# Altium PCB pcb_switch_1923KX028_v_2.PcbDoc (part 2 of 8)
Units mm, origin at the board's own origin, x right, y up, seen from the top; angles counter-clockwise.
Board outline 297.2 x 112.05 mm, 6 copper layers (Component Side, GND Layer 1, Inner Layer 1, Inner Layer 2, GND Layer 2, Solder Side), stack 1.578 mm thick; 545 components, 377 nets, 3174 pads, 1537 vias.
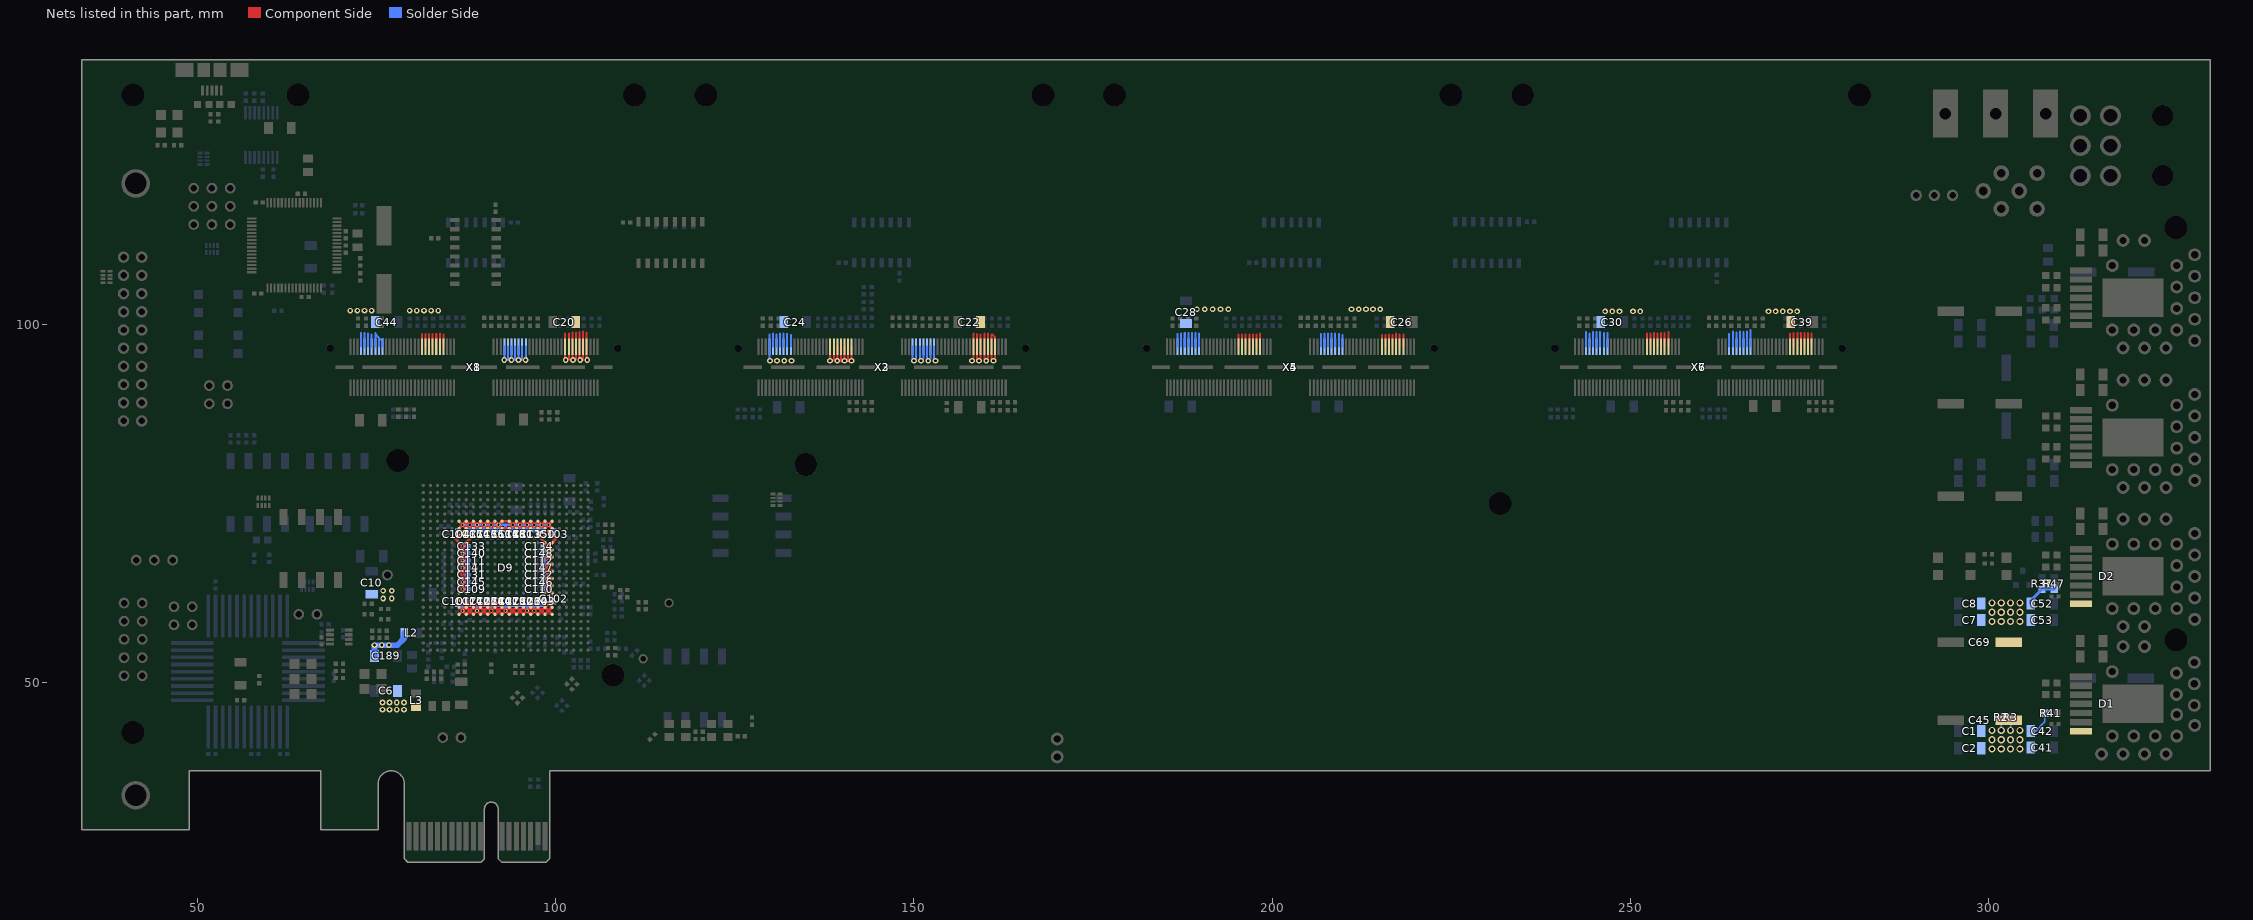
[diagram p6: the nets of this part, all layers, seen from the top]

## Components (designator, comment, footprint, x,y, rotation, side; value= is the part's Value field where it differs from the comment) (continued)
SA6 "DMHA-04G-G" FOOTPRINT_DMHA-04G-G 69.5,76.5 r0 bottom locked
SB1 "7914G-1-000 Е" 7914G_1_000_E 52.9,97.2 r90 bottom
SB2 "7914G-1-000 Е" 7914G_1_000_E 52.9,102.9 r90 bottom
VD1 "KP-2012SYCK" FOOTPRINT_SMD_LED_2.0x1.25mm 302.5,66.2 r270 top
VD2 "KP-2012SYCK" FOOTPRINT_SMD_LED_2.0x1.25mm 297.5,66.2 r270 top
VD3 "KP-2012SYCK" FOOTPRINT_SMD_LED_2.0x1.25mm 47.2,128 r270 top
VD4 "KP-2012SYCK" FOOTPRINT_SMD_LED_2.0x1.25mm 293,66.2 r270 top
VD5 "KP-2012SYCK" FOOTPRINT_SMD_LED_2.0x1.25mm 64.7,52.6 r180 top
VD6 "KP-2012SYCK" FOOTPRINT_SMD_LED_2.0x1.25mm 64.7,50.5 r180 top
VD7 "KP-2012SYCK" FOOTPRINT_SMD_LED_2.0x1.25mm 64.7,48.4 r180 top
VD8 "KP-2012SYCK" FOOTPRINT_SMD_LED_2.0x1.25mm 74.5,49.1 r180 top
VD9 "KP-2012SYCK" FOOTPRINT_SMD_LED_2.0x1.25mm 74.5,51.2 r180 top
VD10 "KP-2012SYCK" FOOTPRINT_SMD_LED_2.0x1.25mm 44.9,128 r270 top
VT1 "BC846B" FOOTPRINT_SOT-23 304.8,64.6 r0 bottom
X1 "qsh-60-01-f-d-a" QSH-60-01-F-D-A#1 70.5,94 r0 top
X2 "qsh-60-01-f-d-a" QSH-60-01-F-D-A#1 127.5,94 r0 top locked
X3 "qsh-60-01-f-d-a" QSH-60-01-F-D-A#2 163.63,94 r180 bottom locked
X4 "qsh-60-01-f-d-a" QSH-60-01-F-D-A#1 184.5,94 r0 top locked
X5 "qsh-60-01-f-d-a" QSH-60-01-F-D-A#2 220.63,94 r180 bottom locked
X6 "qsh-60-01-f-d-a" QSH-60-01-F-D-A#1 241.5,94 r0 top locked
X7 "qsh-60-01-f-d-a" QSH-60-01-F-D-A#2 277.63,94 r180 bottom locked
X8 "qsh-60-01-f-d-a" QSH-60-01-F-D-A#2 106.63,94 r180 bottom
X9 "10104110-0001LF" 10104110-0001LF 52,135.5 r180 top
X10 "WF-3" FOOTPRINT_WF-3 295,118 r180 top
X11 "IDC-20MS" IDC-20MS 39.66,86.5 r270 bottom locked
X12 "45558-0003" 45558-0003 324.35,124.925 r270 top
X13 "hole d=1mm" FOOTPRINT_TESTPOINT#1 76.5,65 r90 top
X14 "hole d=1mm" FOOTPRINT_TESTPOINT#2 112.2,53.3 r90 top
X15 "hole d=1mm" FOOTPRINT_TESTPOINT#3 115.8,61.1 r90 top
X16 "PCI_E x1" PCI_E_x1 91,28.5 r0 top locked
XP1 "PLS-2" PLS-2#1 49.24,59.3 r270 top locked
XP2 "PLS-2" PLS-2#1 85.5,42.3 r0 top
XP3 "PLS-2" PLS-2#1 46.7,59.3 r270 top locked
XP4 "PLS-3" PLS-3 43.97,67.08 r0 top
XP5 "PLD-10" FOOTPRINT_PLD10 41,56 r90 bottom
XP6 "PLS-2" PLS-2#2 52.9,88.9 r180 bottom locked
XP7 "PLS-2" PLS-2#2 52.9,91.44 r180 bottom locked
XP8 "PLS-3" PLS-3 52,119 r0 bottom
XP9 "PLS-3" PLS-3 52,116.46 r0 bottom
XP10 "PLS-3" PLS-3 52,113.92 r0 bottom
XP11 "PLS-2" PLS-2#1 65.4,59.5 r0 top
Z1 "BNX016" BNX016 306.8,116.1 r180 bottom

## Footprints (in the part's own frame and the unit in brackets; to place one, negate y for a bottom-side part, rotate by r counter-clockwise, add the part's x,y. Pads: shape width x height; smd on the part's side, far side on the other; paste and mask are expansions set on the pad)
7914G_1_000_E [mm] "smd key, 5 x 5mm"
  rect 1.27x1.27 smd mask+0.05: 1(-1.27,2.75) 2(1.27,2.75) 3(1.27,-2.75) 4(-1.27,-2.75)
  silkscreen extent -2.5,-2.5 2.5,2.5
45558-0003 [mm] "PCI-Express Card Power Connector"
  round 2.9 hole 1.9 mask+0.1: 1(-4.2,-7.3) 2(0,-7.3) 3(4.2,-7.3) 4(-4.2,-11.5) 5(0,-11.5) 6(4.2,-11.5)
  round 3 hole 3 unplated mask+0.1: 7(-4.2,0) 8(4.2,0)
  silkscreen extent -6.9,-6.2 6.9,6.6
10104110-0001LF [mm] "micro USB B receptacle"
  rect 0.4x1.4 smd mask+0.05: 1(-1.3,2.85) 2(-0.65,2.85) 3(0,2.85) 4(0.65,2.85) 5(1.3,2.85)
  rect 2.5x1.9 smd mask+0.05: 6(-3.85,0) 9(3.85,0)
  rect 1.8x1.9 smd mask+0.05: 7(-1.15,0) 8(1.15,0)
  silkscreen extent -3.75,-1.45 3.75,2.85
BNX016 [mm] "BNX016, Block Type EMIFIL"
  round 2.2 hole 1.2 mask+0.05: 1(5,5) 2(5,0) 3(0,5) 4(0,0) 5(2.5,2.5) 6(7.5,2.5)
  silkscreen extent -3.5,-3 8.5,8
FOOTPRINT_0402 [mm] "0402"
  rect 0.6x0.6 smd mask+0.05: 1(-0.5,0) 2(0.5,0)
  silkscreen extent -1.02,-0.53 1.02,0.53
FOOTPRINT_0603 [mm]
  rect 1x1 smd mask+0.1: 1(-0.8,0) 2(0.8,0)
  silkscreen extent -1.53,-0.73 1.53,0.73
FOOTPRINT_0804_RES_ARRAY [mm] "4 isolated resistor in an 0804 size package"
  rect 0.4x0.7 smd mask+0.05: 1(-0.8,-0.5) 4(0.8,-0.5) 5(-0.8,0.5) 8(0.8,0.5)
  rect 0.3x0.7 smd mask+0.05: 2(-0.25,-0.5) 3(0.25,-0.5) 6(-0.25,0.5) 7(0.25,0.5)
  silkscreen extent -1.07,-0.93 1.07,0.92
FOOTPRINT_0805 [mm] "0805"
  rect 1.1x1.4 smd mask+0.1: 1(-0.95,0) 2(0.95,0)
  silkscreen extent -1.78,-0.98 1.78,0.98
FOOTPRINT_1206#1 [mm] "SMD 1206, 10uF, 10%, 25V, X5R"
  rect 1.2x1.7 smd mask+0.05: 1(-1.6,0) 2(1.6,0)
  silkscreen extent -2.43,-1.08 2.43,1.07
FOOTPRINT_1206#2 [mm] "SMD 1206, 10uF, 10%, 25V, X5R"
  rect 1.2x1.7 smd: 1(-1.6,0) 2(1.6,0)
  silkscreen extent -2.43,-1.08 2.43,1.07
FOOTPRINT_DMHA-04G-G [mm] "DIP SWITCH 4"
  rect 1.1x2.2 smd mask+0.05: 1(-3.81,-4.4) 2(-1.27,-4.4) 3(1.27,-4.4) 4(3.81,-4.4) 5(3.81,4.4) 6(1.27,4.4) 7(-1.27,4.4) 8(-3.81,4.4)
  silkscreen extent -5.08,-3 5.08,3
FOOTPRINT_H14.42-1B [mm] "12 x 12 mm, step 1.0mm, 42 pins,"
  rect 6x0.5 smd mask+0.05: 1(-7.75,-0.5) 2(-7.75,-1.5) 3(-7.75,-2.5) 4(-7.75,-3.5) 5(-7.75,-4.5) 6(-7.75,-5.5) 16(7.75,-5.5) 17(7.75,-4.5) 18(7.75,-3.5) 19(7.75,-2.5) 20(7.75,-1.5) 21(7.75,-0.5) 22(7.75,0.5) 23(7.75,1.5) 24(7.75,2.5) 25(7.75,3.5) 26(7.75,4.5) 27(7.75,5.5) 37(-7.75,5.5) 38(-7.75,4.5) 39(-7.75,3.5) 40(-7.75,2.5) 41(-7.75,1.5) 42(-7.75,0.5)
  rect 0.5x6 smd mask+0.05: 7(-4,-7.75) 8(-3,-7.75) 9(-2,-7.75) 10(-1,-7.75) 11(0,-7.75) 12(1,-7.75) 13(2,-7.75) 14(3,-7.75) 15(4,-7.75) 28(4,7.75) 29(3,7.75) 30(2,7.75) 31(1,7.75) 32(0,7.75) 33(-1,7.75) 34(-2,7.75) 35(-3,7.75) 36(-4,7.75)
  silkscreen extent -6,-6 6,6
FOOTPRINT_KX7 [mm] "GEYER 12.88667 25MHz, 30ppm"
  rect 1.3x1.1 smd mask+0.1: 1(-1.15,-0.9) 2(1.15,-0.9) 3(1.15,0.9) 4(-1.15,0.9)
  silkscreen extent -1.8,-2.3 1.6,1.25
FOOTPRINT_MK8303.576-1 [mm] "BGA 25x25 mm, pitch 1 mm, d = 0.6 mm, 576 balls"
  round 0.45 smd mask+0.05: A1(-11.5,11.5) A2(-10.5,11.5) A3(-9.5,11.5) A4(-8.5,11.5) A5(-7.5,11.5) A6(-6.5,11.5) A7(-5.5,11.5) A8(-4.5,11.5) A9(-3.5,11.5) A10(-2.5,11.5) A11(-1.5,11.5) A12(-0.5,11.5) A13(0.5,11.5) A14(1.5,11.5) A15(2.5,11.5) A16(3.5,11.5) A17(4.5,11.5) A18(5.5,11.5) A19(6.5,11.5) A20(7.5,11.5) A21(8.5,11.5) A22(9.5,11.5) A23(10.5,11.5) A24(11.5,11.5) AA1(-11.5,-8.5) AA2(-10.5,-8.5) AA3(-9.5,-8.5) AA4(-8.5,-8.5) AA5(-7.5,-8.5) AA6(-6.5,-8.5) AA7(-5.5,-8.5) AA8(-4.5,-8.5) AA9(-3.5,-8.5) AA10(-2.5,-8.5) AA11(-1.5,-8.5) AA12(-0.5,-8.5) AA13(0.5,-8.5) AA14(1.5,-8.5) AA15(2.5,-8.5) AA16(3.5,-8.5) AA17(4.5,-8.5) AA18(5.5,-8.5) AA19(6.5,-8.5) AA20(7.5,-8.5) AA21(8.5,-8.5) AA22(9.5,-8.5) AA23(10.5,-8.5) AA24(11.5,-8.5) AB1(-11.5,-9.5) AB2(-10.5,-9.5) AB3(-9.5,-9.5) AB4(-8.5,-9.5) AB5(-7.5,-9.5) AB6(-6.5,-9.5) AB7(-5.5,-9.5) AB8(-4.5,-9.5) AB9(-3.5,-9.5) AB10(-2.5,-9.5) AB11(-1.5,-9.5) AB12(-0.5,-9.5) AB13(0.5,-9.5) AB14(1.5,-9.5) AB15(2.5,-9.5) AB16(3.5,-9.5) AB17(4.5,-9.5) AB18(5.5,-9.5) AB19(6.5,-9.5) AB20(7.5,-9.5) AB21(8.5,-9.5) AB22(9.5,-9.5) AB23(10.5,-9.5) AB24(11.5,-9.5) AC1(-11.5,-10.5) AC2(-10.5,-10.5) AC3(-9.5,-10.5) AC4(-8.5,-10.5) AC5(-7.5,-10.5) AC6(-6.5,-10.5) AC7(-5.5,-10.5) AC8(-4.5,-10.5) AC9(-3.5,-10.5) AC10(-2.5,-10.5) AC11(-1.5,-10.5) AC12(-0.5,-10.5) AC13(0.5,-10.5) AC14(1.5,-10.5) AC15(2.5,-10.5) AC16(3.5,-10.5) AC17(4.5,-10.5) AC18(5.5,-10.5) AC19(6.5,-10.5) AC20(7.5,-10.5) AC21(8.5,-10.5) AC22(9.5,-10.5) AC23(10.5,-10.5) AC24(11.5,-10.5) AD1(-11.5,-11.5) AD2(-10.5,-11.5) AD3(-9.5,-11.5) AD4(-8.5,-11.5) AD5(-7.5,-11.5) AD6(-6.5,-11.5) AD7(-5.5,-11.5) AD8(-4.5,-11.5) AD9(-3.5,-11.5) AD10(-2.5,-11.5) AD11(-1.5,-11.5) AD12(-0.5,-11.5) AD13(0.5,-11.5) AD14(1.5,-11.5) AD15(2.5,-11.5) AD16(3.5,-11.5) AD17(4.5,-11.5) AD18(5.5,-11.5) AD19(6.5,-11.5) AD20(7.5,-11.5) AD21(8.5,-11.5) AD22(9.5,-11.5) AD23(10.5,-11.5) AD24(11.5,-11.5) B1(-11.5,10.5) B2(-10.5,10.5) B3(-9.5,10.5) B4(-8.5,10.5) B5(-7.5,10.5) B6(-6.5,10.5) B7(-5.5,10.5) B8(-4.5,10.5) B9(-3.5,10.5) B10(-2.5,10.5) B11(-1.5,10.5) B12(-0.5,10.5) B13(0.5,10.5) B14(1.5,10.5) B15(2.5,10.5) B16(3.5,10.5) B17(4.5,10.5) B18(5.5,10.5) B19(6.5,10.5) B20(7.5,10.5) B21(8.5,10.5) B22(9.5,10.5) B23(10.5,10.5) B24(11.5,10.5) C1(-11.5,9.5) C2(-10.5,9.5) C3(-9.5,9.5) C4(-8.5,9.5) C5(-7.5,9.5) C6(-6.5,9.5) C7(-5.5,9.5) C8(-4.5,9.5) C9(-3.5,9.5) C10(-2.5,9.5) C11(-1.5,9.5) C12(-0.5,9.5) C13(0.5,9.5) C14(1.5,9.5) C15(2.5,9.5) C16(3.5,9.5) C17(4.5,9.5) C18(5.5,9.5) C19(6.5,9.5) C20(7.5,9.5) C21(8.5,9.5) C22(9.5,9.5) C23(10.5,9.5) C24(11.5,9.5) D1(-11.5,8.5) D2(-10.5,8.5) D3(-9.5,8.5) D4(-8.5,8.5) D5(-7.5,8.5) D6(-6.5,8.5) D7(-5.5,8.5) D8(-4.5,8.5) D9(-3.5,8.5) D10(-2.5,8.5) D11(-1.5,8.5) D12(-0.5,8.5) D13(0.5,8.5) D14(1.5,8.5) D15(2.5,8.5) D16(3.5,8.5) D17(4.5,8.5) D18(5.5,8.5) D19(6.5,8.5) D20(7.5,8.5) D21(8.5,8.5) D22(9.5,8.5) D23(10.5,8.5) D24(11.5,8.5) E1(-11.5,7.5) E2(-10.5,7.5) E3(-9.5,7.5) E4(-8.5,7.5) E5(-7.5,7.5) E6(-6.5,7.5) E7(-5.5,7.5) E8(-4.5,7.5) E9(-3.5,7.5) E10(-2.5,7.5) E11(-1.5,7.5) E12(-0.5,7.5) E13(0.5,7.5) E14(1.5,7.5) E15(2.5,7.5) E16(3.5,7.5) E17(4.5,7.5) E18(5.5,7.5) E19(6.5,7.5) E20(7.5,7.5) E21(8.5,7.5) E22(9.5,7.5) E23(10.5,7.5) E24(11.5,7.5) F1(-11.5,6.5) F2(-10.5,6.5) F3(-9.5,6.5) F4(-8.5,6.5) F5(-7.5,6.5) F6(-6.5,6.5) F7(-5.5,6.5) F8(-4.5,6.5) F9(-3.5,6.5) F10(-2.5,6.5) F11(-1.5,6.5) F12(-0.5,6.5) F13(0.5,6.5) F14(1.5,6.5) F15(2.5,6.5) F16(3.5,6.5) F17(4.5,6.5) F18(5.5,6.5) F19(6.5,6.5) F20(7.5,6.5) F21(8.5,6.5) F22(9.5,6.5) F23(10.5,6.5) F24(11.5,6.5) G1(-11.5,5.5) G2(-10.5,5.5) G3(-9.5,5.5) G4(-8.5,5.5) G5(-7.5,5.5) G6(-6.5,5.5) G7(-5.5,5.5) G8(-4.5,5.5) G9(-3.5,5.5) G10(-2.5,5.5) G11(-1.5,5.5) G12(-0.5,5.5) G13(0.5,5.5) G14(1.5,5.5) G15(2.5,5.5) G16(3.5,5.5) G17(4.5,5.5) G18(5.5,5.5) G19(6.5,5.5) G20(7.5,5.5) G21(8.5,5.5) G22(9.5,5.5) G23(10.5,5.5) G24(11.5,5.5) H1(-11.5,4.5) H2(-10.5,4.5) H3(-9.5,4.5) H4(-8.5,4.5) H5(-7.5,4.5) H6(-6.5,4.5) H7(-5.5,4.5) H8(-4.5,4.5) H9(-3.5,4.5) H10(-2.5,4.5) H11(-1.5,4.5) H12(-0.5,4.5) H13(0.5,4.5) H14(1.5,4.5) H15(2.5,4.5) H16(3.5,4.5) H17(4.5,4.5) H18(5.5,4.5) H19(6.5,4.5) H20(7.5,4.5) H21(8.5,4.5) H22(9.5,4.5) H23(10.5,4.5) H24(11.5,4.5) J1(-11.5,3.5) J2(-10.5,3.5) J3(-9.5,3.5) J4(-8.5,3.5) J5(-7.5,3.5) J6(-6.5,3.5) J7(-5.5,3.5) J8(-4.5,3.5) J9(-3.5,3.5) J10(-2.5,3.5) J11(-1.5,3.5) J12(-0.5,3.5) J13(0.5,3.5) J14(1.5,3.5) J15(2.5,3.5) J16(3.5,3.5) J17(4.5,3.5) J18(5.5,3.5) J19(6.5,3.5) J20(7.5,3.5) J21(8.5,3.5) J22(9.5,3.5) J23(10.5,3.5) J24(11.5,3.5) K1(-11.5,2.5) K2(-10.5,2.5) K3(-9.5,2.5) K4(-8.5,2.5) K5(-7.5,2.5) K6(-6.5,2.5) K7(-5.5,2.5) K8(-4.5,2.5) K9(-3.5,2.5) K10(-2.5,2.5) K11(-1.5,2.5) K12(-0.5,2.5) K13(0.5,2.5) K14(1.5,2.5) K15(2.5,2.5) K16(3.5,2.5) K17(4.5,2.5) K18(5.5,2.5) K19(6.5,2.5) K20(7.5,2.5) K21(8.5,2.5) K22(9.5,2.5) K23(10.5,2.5) K24(11.5,2.5) L1(-11.5,1.5) L2(-10.5,1.5) L3(-9.5,1.5) L4(-8.5,1.5) L5(-7.5,1.5) L6(-6.5,1.5) L7(-5.5,1.5) L8(-4.5,1.5) L9(-3.5,1.5) L10(-2.5,1.5) L11(-1.5,1.5) L12(-0.5,1.5) L13(0.5,1.5) L14(1.5,1.5) L15(2.5,1.5) L16(3.5,1.5) L17(4.5,1.5) L18(5.5,1.5) L19(6.5,1.5) L20(7.5,1.5) L21(8.5,1.5) L22(9.5,1.5) L23(10.5,1.5) L24(11.5,1.5) M1(-11.5,0.5) M2(-10.5,0.5) M3(-9.5,0.5) M4(-8.5,0.5) M5(-7.5,0.5) M6(-6.5,0.5) M7(-5.5,0.5) M8(-4.5,0.5) M9(-3.5,0.5) M10(-2.5,0.5) M11(-1.5,0.5) M12(-0.5,0.5) M13(0.5,0.5) M14(1.5,0.5) M15(2.5,0.5) M16(3.5,0.5) M17(4.5,0.5) M18(5.5,0.5) M19(6.5,0.5) M20(7.5,0.5) M21(8.5,0.5) M22(9.5,0.5) M23(10.5,0.5) M24(11.5,0.5) N1(-11.5,-0.5) N2(-10.5,-0.5) N3(-9.5,-0.5) N4(-8.5,-0.5) N5(-7.5,-0.5) N6(-6.5,-0.5) N7(-5.5,-0.5) N8(-4.5,-0.5) N9(-3.5,-0.5) N10(-2.5,-0.5) N11(-1.5,-0.5) N12(-0.5,-0.5) N13(0.5,-0.5) N14(1.5,-0.5) N15(2.5,-0.5) N16(3.5,-0.5) N17(4.5,-0.5) N18(5.5,-0.5) N19(6.5,-0.5) N20(7.5,-0.5) N21(8.5,-0.5) N22(9.5,-0.5) N23(10.5,-0.5) N24(11.5,-0.5) P1(-11.5,-1.5) P2(-10.5,-1.5) P3(-9.5,-1.5) P4(-8.5,-1.5) P5(-7.5,-1.5) P6(-6.5,-1.5) P7(-5.5,-1.5) P8(-4.5,-1.5) P9(-3.5,-1.5) P10(-2.5,-1.5) P11(-1.5,-1.5) P12(-0.5,-1.5) P13(0.5,-1.5) P14(1.5,-1.5) P15(2.5,-1.5) P16(3.5,-1.5) P17(4.5,-1.5) P18(5.5,-1.5) P19(6.5,-1.5) P20(7.5,-1.5) P21(8.5,-1.5) P22(9.5,-1.5) P23(10.5,-1.5) P24(11.5,-1.5) R1(-11.5,-2.5) R2(-10.5,-2.5) R3(-9.5,-2.5) R4(-8.5,-2.5) R5(-7.5,-2.5) R6(-6.5,-2.5) R7(-5.5,-2.5) R8(-4.5,-2.5) R9(-3.5,-2.5) R10(-2.5,-2.5) R11(-1.5,-2.5) R12(-0.5,-2.5) R13(0.5,-2.5) R14(1.5,-2.5) R15(2.5,-2.5) R16(3.5,-2.5) R17(4.5,-2.5) R18(5.5,-2.5) R19(6.5,-2.5) R20(7.5,-2.5) R21(8.5,-2.5) R22(9.5,-2.5) R23(10.5,-2.5) R24(11.5,-2.5) T1(-11.5,-3.5) T2(-10.5,-3.5) T3(-9.5,-3.5) T4(-8.5,-3.5) T5(-7.5,-3.5) T6(-6.5,-3.5) T7(-5.5,-3.5) T8(-4.5,-3.5) T9(-3.5,-3.5) T10(-2.5,-3.5) T11(-1.5,-3.5) T12(-0.5,-3.5) T13(0.5,-3.5) T14(1.5,-3.5) T15(2.5,-3.5) T16(3.5,-3.5) T17(4.5,-3.5) T18(5.5,-3.5) T19(6.5,-3.5) T20(7.5,-3.5) T21(8.5,-3.5) T22(9.5,-3.5) T23(10.5,-3.5) T24(11.5,-3.5) U1(-11.5,-4.5) U2(-10.5,-4.5) U3(-9.5,-4.5) U4(-8.5,-4.5) U5(-7.5,-4.5) U6(-6.5,-4.5) U7(-5.5,-4.5) U8(-4.5,-4.5) U9(-3.5,-4.5) U10(-2.5,-4.5) U11(-1.5,-4.5) U12(-0.5,-4.5) U13(0.5,-4.5) U14(1.5,-4.5) U15(2.5,-4.5) U16(3.5,-4.5) U17(4.5,-4.5) U18(5.5,-4.5) U19(6.5,-4.5) U20(7.5,-4.5) U21(8.5,-4.5) U22(9.5,-4.5) U23(10.5,-4.5) U24(11.5,-4.5) V1(-11.5,-5.5) V2(-10.5,-5.5) V3(-9.5,-5.5) V4(-8.5,-5.5) V5(-7.5,-5.5) V6(-6.5,-5.5) V7(-5.5,-5.5) V8(-4.5,-5.5) V9(-3.5,-5.5) V10(-2.5,-5.5) V11(-1.5,-5.5) V12(-0.5,-5.5) V13(0.5,-5.5) V14(1.5,-5.5) V15(2.5,-5.5) V16(3.5,-5.5) V17(4.5,-5.5) V18(5.5,-5.5) V19(6.5,-5.5) V20(7.5,-5.5) V21(8.5,-5.5) V22(9.5,-5.5) V23(10.5,-5.5) V24(11.5,-5.5) W1(-11.5,-6.5) W2(-10.5,-6.5) W3(-9.5,-6.5) W4(-8.5,-6.5) W5(-7.5,-6.5) W6(-6.5,-6.5) W7(-5.5,-6.5) W8(-4.5,-6.5) W9(-3.5,-6.5) W10(-2.5,-6.5) W11(-1.5,-6.5) W12(-0.5,-6.5) W13(0.5,-6.5) W14(1.5,-6.5) W15(2.5,-6.5) W16(3.5,-6.5) W17(4.5,-6.5) W18(5.5,-6.5) W19(6.5,-6.5) W20(7.5,-6.5) W21(8.5,-6.5) W22(9.5,-6.5) W23(10.5,-6.5) W24(11.5,-6.5) Y1(-11.5,-7.5) Y2(-10.5,-7.5) Y3(-9.5,-7.5) Y4(-8.5,-7.5) Y5(-7.5,-7.5) Y6(-6.5,-7.5) Y7(-5.5,-7.5) Y8(-4.5,-7.5) Y9(-3.5,-7.5) Y10(-2.5,-7.5) Y11(-1.5,-7.5) Y12(-0.5,-7.5) Y13(0.5,-7.5) Y14(1.5,-7.5) Y15(2.5,-7.5) Y16(3.5,-7.5) Y17(4.5,-7.5) Y18(5.5,-7.5) Y19(6.5,-7.5) Y20(7.5,-7.5) Y21(8.5,-7.5) Y22(9.5,-7.5) Y23(10.5,-7.5) Y24(11.5,-7.5)
  silkscreen extent -12.5,-12.5 12.5,12.5
FOOTPRINT_PLD10 [mm] "PLD-10"
  round 1.5 hole 0.9 mask+0.05: 1(-5.08,-1.27) 2(-5.08,1.27) 3(-2.54,-1.27) 4(-2.54,1.27) 5(0,-1.27) 6(0,1.27) 7(2.54,-1.27) 8(2.54,1.27) 9(5.08,-1.27) 10(5.08,1.27)
  silkscreen extent -6.35,-2.54 6.35,2.54
FOOTPRINT_SMD_LED_2.0x1.25mm [mm] "KP-2012SYCK"
  rect 1.4x1.4 smd mask+0.1: 1(-1.2,0) 2(1.2,0)
  silkscreen extent -3.58,-0.98 2.18,0.98
FOOTPRINT_SOT-23 [mm] "SOT-23"
  rect 0.8x0.9 smd mask+0.1: 1(0.95,1) 2(-0.95,1) 3(0,-1)
  silkscreen extent -1.58,-0.7 1.58,0.7
FOOTPRINT_SVPE_F12 [mm] "SMD type, 10.3 x 10.3 mm"
  rect 1.3x3.7 smd mask+0.05: 1(0,-4.05) 2(0,4.05)
  silkscreen extent -5.15,-5.15 5.15,5.15
FOOTPRINT_TESTPOINT#1 [mm] "hole d=1mm"
  round 1.5 hole 1 mask+0.1: 1(0,0)
  silkscreen extent -1,-1 1,1
FOOTPRINT_TESTPOINT#2 [mm] "hole d=1mm"
  round 1.3 hole 0.8 mask+0.1: 1(0,0)
  silkscreen extent -1,-1 1,1
FOOTPRINT_TESTPOINT#3 [mm] "hole d=1mm"
  round 1.3 hole 0.8: 1(0,0)
  silkscreen extent -1,-1 1,1
FOOTPRINT_WF-3 [mm] "WF-3, 3 pins, step 2.54mm"
  round 1.6 hole 0.9 mask+0.05: 1(0,0) 2(2.54,0) 3(5.08,0)
  silkscreen extent -2.5,-3.3 6.35,2.6
HS49SM [mm] "12.87823"
  rect 5.5x2.1 smd mask+0.05: 1(-4.75,0) 2(4.75,0)
  silkscreen extent -5.7,-2.4 5.7,2.4
IDC-20MS [mm] "IDC-20MS"
  round 1.6 hole 0.9 mask+0.05: 1(0,0) 2(0,-2.54) 3(-2.54,0) 4(-2.54,-2.54) 5(-5.08,0) 6(-5.08,-2.54) 7(-7.62,0) 8(-7.62,-2.54) 9(-10.16,0) 10(-10.16,-2.54) 11(-12.7,0) 12(-12.7,-2.54) 13(-15.24,0) 14(-15.24,-2.54) 15(-17.78,0) 16(-17.78,-2.54) 17(-20.32,0) 18(-20.32,-2.54) 19(-22.86,0) 20(-22.86,-2.54)
  silkscreen extent -27.93,-5.82 5.06,3.26
LMZ22005TZ [mm] "TO-PMOD"
  rect 0.89x3.06 smd mask+0.1: 1(-3.81,-7.28) 2(-2.54,-7.28) 3(-1.27,-7.28) 4(0,-7.28) 5(1.27,-7.28) 6(2.54,-7.28) 7(3.81,-7.28)
  rect 5.35x8.54 smd mask+0.1: 8(0,0)
  silkscreen extent -5.1,-4.6 5.1,-4.6
LQFP64 [mm] "LQFP64"
  rect 0.3x1.3 smd mask+0.05: 1(-3.75,-5.95) 2(-3.25,-5.95) 3(-2.75,-5.95) 4(-2.25,-5.95) 5(-1.75,-5.95) 6(-1.25,-5.95) 7(-0.75,-5.95) 8(-0.25,-5.95) 9(0.25,-5.95) 10(0.75,-5.95) 11(1.25,-5.95) 12(1.75,-5.95) 13(2.25,-5.95) 14(2.75,-5.95) 15(3.25,-5.95) 16(3.75,-5.95) 33(3.75,5.95) 34(3.25,5.95) 35(2.75,5.95) 36(2.25,5.95) 37(1.75,5.95) 38(1.25,5.95) 39(0.75,5.95) 40(0.25,5.95) 41(-0.25,5.95) 42(-0.75,5.95) 43(-1.25,5.95) 44(-1.75,5.95) 45(-2.25,5.95) 46(-2.75,5.95) 47(-3.25,5.95) 48(-3.75,5.95)
  rect 1.3x0.3 smd mask+0.05: 17(5.95,-3.75) 18(5.95,-3.25) 19(5.95,-2.75) 20(5.95,-2.25) 21(5.95,-1.75) 22(5.95,-1.25) 23(5.95,-0.75) 24(5.95,-0.25) 25(5.95,0.25) 26(5.95,0.75) 27(5.95,1.25) 28(5.95,1.75) 29(5.95,2.25) 30(5.95,2.75) 31(5.95,3.25) 32(5.95,3.75) 49(-5.95,3.75) 50(-5.95,3.25) 51(-5.95,2.75) 52(-5.95,2.25) 53(-5.95,1.75) 54(-5.95,1.25) 55(-5.95,0.75) 56(-5.95,0.25) 57(-5.95,-0.25) 58(-5.95,-0.75) 59(-5.95,-1.25) 60(-5.95,-1.75) 61(-5.95,-2.25) 62(-5.95,-2.75) 63(-5.95,-3.25) 64(-5.95,-3.75)
  silkscreen extent -5,-5 5,5
PCI_E_x1 [mm] "PCI-Express x1"
  rect 0.7x3.2 smd far side mask+0.05: A1(-11.5,0.4)
  rect 0.7x4 smd far side mask+0.05: A2(-10.5,0) A3(-9.5,0) A4(-8.5,0) A5(-7.5,0) A6(-6.5,0) A7(-5.5,0) A8(-4.5,0) A9(-3.5,0) A10(-2.5,0) A11(-1.5,0) A12(1.5,0) A13(2.5,0) A14(3.5,0) A15(4.5,0) A16(5.5,0) A17(6.5,0) A18(7.5,0)
  rect 0.7x4 smd mask+0.05: B1(-11.5,0) B2(-10.5,0) B3(-9.5,0) B4(-8.5,0) B5(-7.5,0) B6(-6.5,0) B7(-5.5,0) B8(-4.5,0) B9(-3.5,0) B10(-2.5,0) B11(-1.5,0) B12(1.5,0) B13(2.5,0) B14(3.5,0) B15(4.5,0) B16(5.5,0) B18(7.5,0)
  rect 0.7x3.2 smd mask+0.05: B17(6.5,0.4)
PLS-2#1 [mm] "PLS-2"
  round 1.5 hole 0.9 mask+0.1: 1(-1.27,0) 2(1.27,0)
  silkscreen extent -3.6,-1.27 2.54,1.27
PLS-2#2 [mm] "PLS-2"
  round 1.5 hole 0.9: 1(-1.27,0) 2(1.27,0)
  silkscreen extent -3.6,-1.27 2.54,1.27
PLS-3 [mm] "PSL-3"
  round 1.5 hole 0.9 mask+0.05: 1(-2.54,0) 2(0,0) 3(2.54,0)
  silkscreen extent -4.83,-1.27 3.81,1.27
pwr_switch [mm] "pwr switch 3x7mm 18x13"
  rect 6.7x3.5 hole 1.6 slot 5.5 at 0 deg mask+0.1: 1(0,-7) 2(0,0) 3(0,7)
  silkscreen extent -6.5,-9.5 6.5,9.5
QSH-60-01-F-D-A#1 [mm] "Samtec, high-speed socket, pitch 0,5 mm, 120 pins"
  round 1.05 hole 1.05 unplated mask+0.05: 0(-2,2.67) 0(38.13,2.67)
  rect 0.28x2.3 smd mask+0.05: 1(0.815,-2.865) 2(0.815,2.865) 3(1.315,-2.865) 4(1.315,2.865) 5(1.815,-2.865) 6(1.815,2.865) 7(2.315,-2.865) 8(2.315,2.865) 9(2.815,-2.865) 10(2.815,2.865) 11(3.315,-2.865) 12(3.315,2.865) 13(3.815,-2.865) 14(3.815,2.865) 15(4.315,-2.865) 16(4.315,2.865) 17(4.815,-2.865) 18(4.815,2.865) 19(5.315,-2.865) 20(5.315,2.865) 21(5.815,-2.865) 22(5.815,2.865) 23(6.315,-2.865) 24(6.315,2.865) 25(6.815,-2.865) 26(6.815,2.865) 27(7.315,-2.865) 28(7.315,2.865) 29(7.815,-2.865) 30(7.815,2.865) 31(8.315,-2.865) 32(8.315,2.865) 33(8.815,-2.865) 34(8.815,2.865) 35(9.315,-2.865) 36(9.315,2.865) 37(9.815,-2.865) 38(9.815,2.865) 39(10.315,-2.865) 40(10.315,2.865) 41(10.815,-2.865) 42(10.815,2.865) 43(11.315,-2.865) 44(11.315,2.865) 45(11.815,-2.865) 46(11.815,2.865) 47(12.315,-2.865) 48(12.315,2.865) 49(12.815,-2.865) 50(12.815,2.865) 51(13.315,-2.865) 52(13.315,2.865) 53(13.815,-2.865) 54(13.815,2.865) 55(14.315,-2.865) 56(14.315,2.865) 57(14.815,-2.865) 58(14.815,2.865) 59(15.315,-2.865) 60(15.315,2.865) 61(20.82,-2.865) 62(20.82,2.865) 63(21.32,-2.865) 64(21.32,2.865) 65(21.82,-2.865) 66(21.82,2.865) 67(22.32,-2.865) 68(22.32,2.865) 69(22.82,-2.865) 70(22.82,2.865) 71(23.32,-2.865) 72(23.32,2.865) 73(23.82,-2.865) 74(23.82,2.865) 75(24.32,-2.865) 76(24.32,2.865) 77(24.82,-2.865) 78(24.82,2.865) 79(25.32,-2.865) 80(25.32,2.865) 81(25.82,-2.865) 82(25.82,2.865) 83(26.32,-2.865) 84(26.32,2.865) 85(26.82,-2.865) 86(26.82,2.865) 87(27.32,-2.865) 88(27.32,2.865) 89(27.82,-2.865) 90(27.82,2.865) 91(28.32,-2.865) 92(28.32,2.865) 93(28.82,-2.865) 94(28.82,2.865) 95(29.32,-2.865) 96(29.32,2.865) 97(29.82,-2.865) 98(29.82,2.865) 99(30.32,-2.865) 100(30.32,2.865) 101(30.82,-2.865) 102(30.82,2.865) 103(31.32,-2.865) 104(31.32,2.865) 105(31.82,-2.865) 106(31.82,2.865) 107(32.32,-2.865) 108(32.32,2.865) 109(32.82,-2.865) 110(32.82,2.865) 111(33.32,-2.865) 112(33.32,2.865) 113(33.82,-2.865) 114(33.82,2.865) 115(34.32,-2.865) 116(34.32,2.865) 117(34.82,-2.865) 118(34.82,2.865) 119(35.32,-2.865) 120(35.32,2.865)
  rect 2.54x0.43 smd: 121(0,0) 124(16.13,0) 125(20,0) 128(36.13,0)
  rect 4.7x0.43 smd: 122(4.89,0) 123(11.24,0) 126(24.89,0) 127(31.24,0)
  silkscreen extent -2.6,-3.8 38.7,3.8
QSH-60-01-F-D-A#2 [mm] "Samtec, high-speed socket, pitch 0,5 mm, 120 pins"
  round 1.05 hole 1.05 unplated mask+0.05: 0(-2,2.67) 0(38.13,2.67)
  rect 0.28x2.3 smd: 1(0.815,-2.865) 2(0.815,2.865) 3(1.315,-2.865) 4(1.315,2.865) 5(1.815,-2.865) 6(1.815,2.865) 7(2.315,-2.865) 8(2.315,2.865) 9(2.815,-2.865) 10(2.815,2.865) 11(3.315,-2.865) 12(3.315,2.865) 13(3.815,-2.865) 14(3.815,2.865) 15(4.315,-2.865) 16(4.315,2.865) 17(4.815,-2.865) 18(4.815,2.865) 19(5.315,-2.865) 20(5.315,2.865) 21(5.815,-2.865) 22(5.815,2.865) 23(6.315,-2.865) 24(6.315,2.865) 25(6.815,-2.865) 26(6.815,2.865) 27(7.315,-2.865) 28(7.315,2.865) 29(7.815,-2.865) 30(7.815,2.865) 31(8.315,-2.865) 32(8.315,2.865) 33(8.815,-2.865) 34(8.815,2.865) 35(9.315,-2.865) 36(9.315,2.865) 37(9.815,-2.865) 38(9.815,2.865) 39(10.315,-2.865) 40(10.315,2.865) 41(10.815,-2.865) 42(10.815,2.865) 43(11.315,-2.865) 44(11.315,2.865) 45(11.815,-2.865) 46(11.815,2.865) 47(12.315,-2.865) 48(12.315,2.865) 49(12.815,-2.865) 50(12.815,2.865) 51(13.315,-2.865) 52(13.315,2.865) 53(13.815,-2.865) 54(13.815,2.865) 55(14.315,-2.865) 56(14.315,2.865) 57(14.815,-2.865) 58(14.815,2.865) 59(15.315,-2.865) 60(15.315,2.865) 61(20.82,-2.865) 62(20.82,2.865) 63(21.32,-2.865) 64(21.32,2.865) 65(21.82,-2.865) 66(21.82,2.865) 67(22.32,-2.865) 68(22.32,2.865) 69(22.82,-2.865) 70(22.82,2.865) 71(23.32,-2.865) 72(23.32,2.865) 73(23.82,-2.865) 74(23.82,2.865) 75(24.32,-2.865) 76(24.32,2.865) 77(24.82,-2.865) 78(24.82,2.865) 79(25.32,-2.865) 80(25.32,2.865) 81(25.82,-2.865) 82(25.82,2.865) 83(26.32,-2.865) 84(26.32,2.865) 85(26.82,-2.865) 86(26.82,2.865) 87(27.32,-2.865) 88(27.32,2.865) 89(27.82,-2.865) 90(27.82,2.865) 91(28.32,-2.865) 92(28.32,2.865) 93(28.82,-2.865) 94(28.82,2.865) 95(29.32,-2.865) 96(29.32,2.865) 97(29.82,-2.865) 98(29.82,2.865) 99(30.32,-2.865) 100(30.32,2.865) 101(30.82,-2.865) 102(30.82,2.865) 103(31.32,-2.865) 104(31.32,2.865) 105(31.82,-2.865) 106(31.82,2.865) 107(32.32,-2.865) 108(32.32,2.865) 109(32.82,-2.865) 110(32.82,2.865) 111(33.32,-2.865) 112(33.32,2.865) 113(33.82,-2.865) 114(33.82,2.865) 115(34.32,-2.865) 116(34.32,2.865) 117(34.82,-2.865) 118(34.82,2.865) 119(35.32,-2.865) 120(35.32,2.865)
  rect 2.54x0.43 smd: 121(0,0) 124(16.13,0) 125(20,0) 128(36.13,0)
  rect 4.7x0.43 smd: 122(4.89,0) 123(11.24,0) 126(24.89,0) 127(31.24,0)
  silkscreen extent -2.6,-3.8 38.7,3.8
SOIC-14 [mm] "SOIC-14, pitch 1.27mm, 14 pins"
  rect 0.6x1.35 smd mask+0.05: 1(-3.81,-2.8) 2(-2.54,-2.8) 3(-1.27,-2.8) 4(0,-2.8) 5(1.27,-2.8) 6(2.54,-2.8) 7(3.81,-2.8) 8(3.81,2.8) 9(2.54,2.8) 10(1.27,2.8) 11(0,2.8) 12(-1.27,2.8) 13(-2.54,2.8) 14(-3.81,2.8)
  silkscreen extent -4.4,-1.9 4.4,1.9
SOIC-16 [mm] "pitch 1.27, 16 pins, 9.9 x 5.9 mm"
  rect 0.6x1.35 smd mask+0.05: 1(-4.445,-2.9) 2(-3.175,-2.9) 3(-1.905,-2.9) 4(-0.635,-2.9) 5(0.635,-2.9) 6(1.905,-2.9) 7(3.175,-2.9) 8(4.445,-2.9) 9(4.445,2.9) 10(3.175,2.9) 11(1.905,2.9) 12(0.635,2.9) 13(-0.635,2.9) 14(-1.905,2.9) 15(-3.175,2.9) 16(-4.445,2.9)
  silkscreen extent -5,-1.9 5,1.9
SOT-23 [mm] "TEMPERATURE SENSOR"
  rect 0.45x1.1 smd mask+0.05: 1(0,0) 2(0.65,0) 3(1.3,0) 4(1.95,0) 5(1.95,2.6) 6(1.3,2.6) 7(0.65,2.6) 8(0,2.6)
  silkscreen extent -0.53,0.5 2.47,2.1
SSOP-16 [mil] "pitch 0.635mm, 16 pins, 4.9 x 5.99 mm"
  rect 15x73 smd mask+1.97: 1(-87.5,-123) 2(-62.5,-123) 3(-37.5,-123) 4(-12.5,-123) 5(12.5,-123) 6(37.5,-123) 7(62.5,-123) 8(87.5,-123) 9(87.5,123) 10(62.5,123) 11(37.5,123) 12(12.5,123) 13(-12.5,123) 14(-37.5,123) 15(-62.5,123) 16(-87.5,123)
  silkscreen extent -99,-77 99,77

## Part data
BQ1: library part Quartz_Crystal_HC49_S, "GEYER 12.87823"
BQ2: library part Quartz_Crystal, "GEYER 12.88667"
C1 C2 C4 C5 C6 C7 C8 C10 C12 C13 C16 C17 C19 C20 C21 C22 C23 C24 C25 C26 C27 C28 C29 C30 C35 C39 C40 C44: library part Cap_1206, "GRM31CR60J107ME39L"
C3 C9: library part Cap, "0402ZD104KAT2A"
C11 C15 C18 C31 C32 C33 C34 C48 C49 C54 C55 C57 C60 C61 C62 C63 C64 C67 C68 C72 C73 C76 C77 C79 C80 C81 C82 C84 C86 C87 C88 C89 C90 C91 C92 C93 C96 C97 C98 C99 C100 C105 C106 C107 C109 C110 C111 C112 C113 C114 C115 C118 C119 C122 C123 C124 C125 C126 C165 C166 C167 C168 C169 C170 C173 C174 C175 C176 C177 C178 C179 C185 C186 C191 C192 C194 C202 C204 C205 C206 C207 C208 C209 C210 C212 C217 C218 C219 C220 C222 C223 C227 C238: library part Cap_0402, "0402ZD104KAT2A"
C14 C78: library part Cap, "0603YC474KAT2A"
C36 C45 C56 C69 C83 C85 C188 C190: library part Cap_pol_OSCON_16SVPE470M, "16SVPE470M"
C37 C38 C41 C42 C43 C46 C47 C52 C53 C58 C59 C65 C66 C70 C71 C74 C75 C149 C171 C172 C189: library part Cap_1206, "12063D106KAT2A"
C50 C51: library part Cap, "CGA3E2C0G1H470J080AA"
C94 C95 C116 C117: library part Cap_0402, "04025A180JAT2A"
C101 C102 C103 C104 C156 C157 C158 C159 C160 C161 C162 C163 C164 C195 C213 C214 C215 C216 C221: library part Cap_0402, "0402ZD105KAT2A"
C108 C127 C128 C129 C130 C131 C132 C133 C134 C135 C136 C137 C138 C180 C181 C182 C183 C184 C187: library part Cap_0402, "04023C103KAT2A"
C120: library part Cap_0402, "04025A101JAT2A"
C121 C239: library part Cap_1210, "GRM31CR60J107ME39L"
C139 C140 C141 C142 C143 C144 C145 C146 C147 C148 C150 C151 C152 C153 C154 C155 C193 C196 C197 C198 C199 C200 C201 C203 C211 C224 C225 C226 C228 C229 C230 C231 C232 C233 C234 C235 C236 C237: library part Cap_0402, "04025C102KAT2A"
D5 D6 D7 D8: "4 buffers with 3-state outputs"
D9: "Milandr, 16 ports Ethernet Switch 1000/100/10"
D10: library part TMP421, "TMP421"
D11: library part MCU_1986BE92Q, "Milandr, 32-bit MCU"
D12: "USB to BASIC UART IC"
D13: library part 1636RR3, "Flash 512KB, H14.42-1B, Milandr"
D14 D15: "8-Bit Shift Registers With 3-State Output Registers"
D16: library part TCA9546A, "Low Voltage 4-Channel I2C and SMBus Switch with Reset Function"
G1: library part Oscillator, "GEYER 12.95000"
L1 L2 L3 L4 L5 L6: library part L_0805, "BLM21PG331SN1"
R1 R30 R34: library part Res_0805, "CR0805-FX-4021ELF"
R2 R3 R11 R12 R33 R140 R143 R145 R162 R163: library part Res, "CR0402-FX-2800GLF"
R4 R5: library part Res, "CR0603-JW-681ELF"
R6 R9 R10 R13 R15 R109 R110 R116 R117 R118 R119 R120 R134 R135 R136 R137 R141 R142 R144 R152 R153 R161 R164 R165 R167 R171 R173 R175 R176 R177 R180 R181 R182 R183 R184 R185 R228 R229 R230 R231 R232 R233 R234: library part Res, "CR0402-FX-1102GLF"
R7 R8 R102 R111 R225 R226 R227: library part Res, "RC0402FR-0724RL"
R14 R16 R21 R22 R23 R24 R35 R38 R39 R42 R45 R48 R62 R63 R64 R65 R66 R67 R70 R71 R78 R79 R80 R81 R82 R83 R86 R87 R88 R89 R90 R91 R96 R97 R105 R106 R107 R108 R114 R115 R121 R122 R123 R124 R125 R126 R127 R128 R129 R130 R131 R132 R133 R146 R147 R148 R149 R150 R151 R154 R155 R156 R157 R158 R159 R186 R187 R188 R189 R190 R191 R192 R193 R194 R195 R196 R197 R198 R199 R200 R201 R202 R203 R204 R205 R206 R207 R208 R209 R210 R211 R212 R213 R214 R215 R216 R217 R218 R219 R220 R221 R222 R223 R224: library part Res_0402, "CR0402-FX-2491GLF"
R17 R18 R19 R20 R25 R26 R51 R59 R60 R61 R68 R69 R74 R75 R84 R85 R92 R93 R94 R95 R98 R99 R101 R103 R112 R113: library part Res_0402, "CR0402-FX-1102GLF"
R27 R28 R29 R32 R72 R73 R76 R77: library part Res_0402, "CR0402-FX-6041GLF"
R31: library part Res, "CR0603-FX-49R9ELF"
R36 R43: library part Res, "CR0603-FX-5230ELF"
R37: library part Res, "CR0603-FX-3322ELF"
R40 R46: library part Res, "CR0603-FX-4700ELF"
R41 R47 R160: library part Res, "CR0603-FX-2001ELF"
R44 R50 R52 R53 R56 R57: library part Res, "CR0603-FX-5231ELF"
R49 R55: library part Res, "CR0603-FX-3572ELF"
R54 R58: library part Res, "CR0603-FX-1651ELF"
R100 R104: library part Res_0402, "CR0402-FX-1821GLF"
R138 R139: library part Res, "RC0402FR-0749R9L"
R166 R168: library part Res_0402, "CR0402-FX-2000GLF"
R169 R170 R172 R174 R178 R179: library part RES_ARRAY_YC124_YAGEO, "YC124-JR-0710KL"
SA1: library part pwr_switch, "768, Переключатель, 2 конт., 250В/6.0А"
SA2 SA3 SA4 SA5 SA6: library part dip_switch, "dip_switch (4 poles)"
SB1 SB2: library part KEY_BOURNS_7914G_1_000_E, "smd key, 5 x 5 mm, h = 1.65 mm"
VD1 VD2 VD3 VD4 VD5 VD6 VD7 VD8 VD9 VD10: library part Vd_led, "kingbright 2.0 x 1.25mm SMD CHIP LED LAMP"
VT1: library part VT
X1 X2 X3 X4 X5 X6 X7 X8: "Samtec, high-speed socket, pitch 0.5 mm, 120 pins"
X9: "MICRO USB B TYPE RECEPTACLE"
X10: "Plug for board, 3 pins, step 2.54mm"
X13 X14 X15: library part TestPoint, "test point"
X16: library part PCI_Express_x1, "PCI-Express x1"
XP5: "PLD-10, step 2.54 mm"

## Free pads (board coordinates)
  round 3.175 hole 3.2 unplated mask+0.05: 0(41,43) 0(41,132) 0(64,132) 0(78,81) 0(108,51) 0(111,132) 0(121,132) 0(134.9,80.4) 0(168,132) 0(178,132) 0(225,132) 0(231.8,75) 0(235,132) 0(282,132) 0(326.2,55.9) 0(326.2,113.5)
  round 4 hole 3 mask+0.05: 0(41.35,34.25) 0(41.35,119.65)
  round 1.8 hole 1: 0(170,39.6) 0(170,42.1) 0(315.8,40) 0(317.3,42.5) 0(317.3,51.5) 0(317.3,60.3) 0(317.3,69.3) 0(317.3,79.7) 0(317.3,88.7) 0(317.3,99.2) 0(317.3,108.2) 0(318.8,40) 0(318.8,55) 0(318.8,57.8) 0(318.8,72.8) 0(318.8,77.2) 0(318.8,92.2) 0(318.8,96.7) 0(318.8,111.7) 0(320.3,42.5) 0(320.3,60.3) 0(320.3,69.3) 0(320.3,79.7) 0(320.3,99.2) 0(321.8,40) 0(321.8,55) 0(321.8,57.8) 0(321.8,77.2) 0(321.8,96.7) 0(321.8,111.7) 0(321.8,72.8) 0(321.8,92.2) 0(323.3,42.5) 0(323.3,60.3) 0(323.3,79.7) 0(323.3,99.2) 0(323.3,69.3) 0(324.8,40) 0(324.8,72.8) 0(324.8,77.2) 0(324.8,92.2) 0(324.8,96.7) 0(326.25,48.3) 0(326.25,51.3) 0(326.3,42.5) 0(326.3,45.5) 0(326.3,60.3) 0(326.3,63.3) 0(326.3,66.3) 0(326.3,69.3) 0(326.3,79.7) 0(326.3,82.7) 0(326.3,85.7) 0(326.3,88.7) 0(326.3,99.2) 0(326.3,102.2) 0(326.3,105.2) 0(326.3,108.2) 0(328.75,46.8) 0(328.75,49.8) 0(328.75,52.8) 0(328.8,44) 0(328.8,58.8) 0(328.8,61.8) 0(328.8,64.8) 0(328.8,67.8) 0(328.8,70.8) 0(328.8,78.2) 0(328.8,81.2) 0(328.8,84.2) 0(328.8,87.2) 0(328.8,90.2) 0(328.8,97.7) 0(328.8,100.7) 0(328.8,103.7) 0(328.8,106.7) 0(328.8,109.7)

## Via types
v1: diameter 0.8, hole 0.4, Component Side to Solder Side, tented both sides, 884 vias
v2: diameter 0.5, hole 0.3, Component Side to Solder Side, tented both sides, 269 vias
v3: diameter 1, hole 0.6, Component Side to Solder Side, tented both sides, 95 vias
v4: diameter 0.5/0.5/0.3/0.3/0.5/0.5 (per signal layer), hole 0.3, Component Side to Solder Side, tented both sides, 80 vias
v5: diameter 0.5/0.3/0.3/0.5/0.3/0.5 (per signal layer), hole 0.3, Component Side to Solder Side, tented both sides, 37 vias
v6: diameter 0.5/0.3/0.3/0.3/0.3/0.5 (per signal layer), hole 0.3, Component Side to Solder Side, tented both sides, 34 vias
v7: diameter 0.5/0.5/0.5/0.3/0.5/0.5 (per signal layer), hole 0.3, Component Side to Solder Side, tented both sides, 29 vias
v8: diameter 0.5, hole 0.3, Component Side to Solder Side, 25 vias
v9: diameter 0.5/0.3/0.5/0.3/0.3/0.5 (per signal layer), hole 0.3, Component Side to Solder Side, tented both sides, 25 vias
v10: diameter 0.5/0.5/0.3/0.5/0.5/0.5 (per signal layer), hole 0.3, Component Side to Solder Side, tented both sides, 19 vias
v11: diameter 0.6, hole 0.3, Component Side to Solder Side, tented both sides, 14 vias
v12: diameter 0.8, hole 0.5, Component Side to Solder Side, tented both sides, 11 vias
v13: diameter 0.5/0.3/0.5/0.5/0.3/0.5 (per signal layer), hole 0.3, Component Side to Solder Side, tented both sides, 7 vias
v14: diameter 0.8, hole 0.4, Component Side to Solder Side, 5 vias
v15: diameter 0.5/0.5/0.5/0.5/0.5/0.5 (per signal layer), hole 0.3, Component Side to Solder Side, tented both sides, 2 vias
v16: diameter 0.8, hole 0.5, Component Side to Solder Side, 1 vias

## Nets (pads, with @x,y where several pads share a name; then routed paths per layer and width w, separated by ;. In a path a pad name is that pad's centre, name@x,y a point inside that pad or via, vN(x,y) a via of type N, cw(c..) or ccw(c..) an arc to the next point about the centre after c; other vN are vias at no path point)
+1.1V: C1.1 C2.1 C6.1 C7.1 C8.1 C10.1 C20.1 C22.1 C24.1 C26.1 C28.1 C30.1 C39.1 C41.1 C42.1 C44.1 C45.1 C52.1 C53.1 C69.1 C101.1 C102.1 C103.1 C104.1 C105.1 C106.1 C107.1 C109.1 C110.1 C111.1 C112.1 C113.1 C114.1 C115.1 C127.1 C128.1 C129.1 C130.1 C131.1 C132.1 C133.1 C134.1 C135.1 C136.1 C137.1 C138.1 C140.1 C141.1 C142.1 C143.1 C144.1 C145.1 C146.1 C147.1 C148.1 C150.1 C151.1 C152.1 C153.1 C154.1 C189.1 D1.7 D2.7 D9.F6 D9.F7 D9.F8 D9.F9 D9.F10 D9.F11 D9.F12 D9.F13 D9.F14 D9.F15 D9.F16 D9.F17 D9.F18 D9.F19 D9.G6 D9.G7 D9.G8 D9.G9 D9.G10 D9.G11 D9.G12 D9.G13 D9.G14 D9.G15 D9.G16 D9.G17 D9.G18 D9.G19 D9.H6 D9.H7 D9.H18 D9.H19 D9.J6 D9.J7 D9.J18 D9.J19 D9.K6 D9.K7 D9.K18 D9.K19 D9.L6 D9.L7 D9.L18 D9.L19 D9.M6 D9.M7 D9.M18 D9.M19 D9.N6 D9.N7 D9.N18 D9.N19 D9.P6 D9.P7 D9.P18 D9.P19 D9.R6 D9.R7 D9.R18 D9.R19 D9.T6 D9.T7 D9.T18 D9.T19 D9.U6 D9.U7 D9.U10 D9.U11 D9.U18 D9.U19 D9.V6 D9.V7 D9.V8 D9.V9 D9.V10 D9.V11 D9.V12 D9.V13 D9.V14 D9.V15 D9.V16 D9.V17 D9.V18 D9.V19 D9.W6 D9.W7 D9.W8 D9.W9 D9.W10 D9.W11 D9.W12 D9.W13 D9.W14 D9.W15 D9.W16 D9.W17 D9.W18 D9.W19 L2.1 L3.2 R2.2 R3.2 R37.1 R41.2 R47.2 X1.42 X1.44 X1.46 X1.48 X1.50 X1.52 X1.54 X1.102 X1.104 X1.106 X1.108 X1.110 X1.112 X1.114 X2.42 X2.44 X2.46 X2.48 X2.50 X2.52 X2.54 X2.102 X2.104 X2.106 X2.108 X2.110 X2.112 X2.114 X3.42 X3.44 X3.46 X3.48 X3.50 X3.52 X3.54 X3.102 X3.104 X3.106 X3.108 X3.110 X3.112 X3.114 X4.42 X4.44 X4.46 X4.48 X4.50 X4.52 X4.54 X4.102 X4.104 X4.106 X4.108 X4.110 X4.112 X4.114 X5.42 X5.44 X5.46 X5.48 X5.50 X5.52 X5.54 X5.102 X5.104 X5.106 X5.108 X5.110 X5.112 X5.114 X6.42 X6.44 X6.46 X6.48 X6.50 X6.52 X6.54 X6.102 X6.104 X6.106 X6.108 X6.110 X6.112 X6.114 X7.42 X7.44 X7.46 X7.48 X7.50 X7.52 X7.54 X7.102 X7.104 X7.106 X7.108 X7.110 X7.112 X7.114 X8.42 X8.44 X8.46 X8.48 X8.50 X8.52 X8.54 X8.102 X8.104 X8.106 X8.108 X8.110 X8.112 X8.114 | length 482
  Component Side w0.2: D9.U19@99.5,61.5 D9.T19@99.5,62.5
  Component Side w0.28: X1.42@81.315,96.865 81.315,98.615 ; X1.44@81.815,96.865 81.815,98.615 ; X1.46@82.315,96.865 82.315,98.615 ; X1.48@82.815,96.865 82.815,98.615 ; X1.50@83.315,96.865 83.315,98.615 ; X1.52@83.815,96.865 83.815,98.715 ; X1.54@84.315,96.865 84.315,98.585 ; v1@101.32,95.08 X1.102@101.32,96.865 101.32,98.72 ; 101.82,95.08 X1.104@101.82,96.865 101.82,98.72 ; v1@102.32,95.08 X1.106@102.32,96.865 102.32,98.88 ; 102.82,95.08 X1.108@102.82,96.865 102.82,98.82 ; v1@103.32,95.08 X1.110@103.32,96.865 103.32,98.92 ; 103.82,94.98 X1.112@103.82,96.865 103.82,98.98 ; v1@104.32,95.08 X1.114@104.32,96.865 104.32,98.88 ; v1@138.315,94.915 X2.42@138.315,96.865 ; 138.815,94.915 X2.44@138.815,96.865 ; v1@139.315,94.915 X2.46@139.315,96.865 ; 139.815,94.815 X2.48@139.815,96.865 ; v1@140.315,94.915 X2.50@140.315,96.865 ; 140.815,94.815 X2.52@140.815,96.865 ; v1@141.315,94.915 X2.54@141.315,96.865 ; v1@158.32,95.12 X2.102@158.32,96.865 158.32,98.68 ; v1@158.82,95.18 X2.104@158.82,96.865 158.82,98.62 ; v1@159.32,95.12 X2.106@159.32,96.865 159.32,98.58 ; v1@159.82,95.18 X2.108@159.82,96.865 159.82,98.68 ; v1@160.32,95.12 X2.110@160.32,96.865 160.32,98.68 ; v1@160.82,95.18 X2.112@160.82,96.865 160.82,98.58 ; 160.92,98.58 161.32,98.18 X2.114@161.32,96.865 v1@161.32,95.12 ; X4.42@195.315,96.865 195.315,98.585 ; X4.44@195.815,96.865 195.815,98.585 ; X4.46@196.315,96.865 196.315,98.585 ; X4.48@196.815,96.865 196.815,98.585 ; X4.50@197.315,96.865 197.315,98.585 ; X4.52@197.815,96.865 197.815,98.585 ; X4.54@198.315,96.865 198.315,98.685 ; X4.102@215.32,96.865 215.32,98.52 ; X4.104@215.82,96.865 215.82,98.52 ; X4.106@216.32,96.865 216.32,98.58 ; X4.108@216.82,96.865 216.82,98.52 ; X4.110@217.32,96.865 217.32,98.68 ; X4.112@217.82,96.865 217.82,98.58 ; X4.114@218.32,96.865 218.32,98.58 ; X6.42@252.315,96.865 252.315,98.685 ; X6.44@252.815,96.865 252.815,98.715 ; X6.46@253.315,96.865 253.315,98.785 ; X6.48@253.815,96.865 253.815,98.685 ; X6.50@254.315,96.865 254.315,98.785 ; X6.52@254.815,96.865 254.815,98.785 ; X6.54@255.315,96.865 255.315,98.885 ; X6.102@272.32,96.865 272.32,98.68 ; X6.104@272.82,96.865 272.82,98.78 ; X6.106@273.32,96.865 273.32,98.78 ; 273.8,98.8 273.82,98.78 X6.108@273.82,96.865 ; X6.110@274.32,96.865 274.32,98.78 ; X6.112@274.82,96.865 274.82,98.78 ; X6.114@275.32,96.865 275.32,98.68
  Component Side w0.4: D9.W6@86.5,59.5 v5(87,60) ; D9.U6@86.5,61.5 v5(87,61) ; D9.T6@86.5,62.5 v5(87,63) ; D9.F6@86.5,72.5 v5(87,72) ; D9.T7@87.5,62.5 v5(87,63) ; D9.W17@97.5,59.5 v5(97,60) ; D9.W17@97.5,59.5 98,60 ; D9.U18@98.5,61.5 v5(99,61) ; D9.T18@98.5,62.5 v5(99,63) ; D9.W19@99.5,59.5 99,60 ; D9.U19@99.5,61.5 v5(99,61) ; D9.T19@99.5,62.5 v5(99,63) ; D9.J19@99.5,69.5 v5(99,69) ; D9.F19@99.5,72.5 v5(99,72) ; D9.J19@99.5,69.5 100,70 D9.H19@99.5,70.5 v5(99,71) ; v5(87,60) D9.V6@86.5,60.5 v5(87,61) ; v5(87,60) D9.W7@87.5,59.5 88,60 ; v5(87,60) D9.V7@87.5,60.5 ; v5(87,61) D9.U7@87.5,61.5 88,61 ; v5(87,61) D9.V7@87.5,60.5 ; v5(87,63) D9.R6@86.5,63.5 v5(87,64) ; v5(87,63) D9.R7@87.5,63.5 v5(87,64) ; v5(87,64) D9.P7@87.5,64.5 87,65 ; v5(87,64) D9.P6@86.5,64.5 87,65 ; 87,65 D9.N6@86.5,65.5 v5(87,66) ; 87,65 D9.N7@87.5,65.5 v5(87,66) ; v5(87,66) D9.M6@86.5,66.5 v5(87,67) ; v5(87,66) D9.M7@87.5,66.5 v5(87,67) ; v5(87,67) D9.L7@87.5,67.5 v5(87,68) ; v5(87,67) D9.L6@86.5,67.5 v5(87,68) ; v5(87,68) D9.K7@87.5,68.5 v5(87,69) ; v5(87,68) D9.K6@86.5,68.5 v5(87,69) ; v5(87,69) D9.J6@86.5,69.5 86,70 D9.H6@86.5,70.5 v5(87,71) ; v5(87,69) D9.J7@87.5,69.5 88,70 D9.H7@87.5,70.5 v5(87,71) ; v5(87,71) D9.G7@87.5,71.5 ; v5(87,71) D9.G6@86.5,71.5 v5(87,72) ; v5(87,72) D9.G7@87.5,71.5 ; v5(87,72) D9.F7@87.5,72.5 v5(88,72) ; D9.V7@87.5,60.5 88,60 ; D9.V7@87.5,60.5 88,61 ; D9.G7@87.5,71.5 v5(88,72) ; 88,60 D9.W8@88.5,59.5 v5(89,60) ; 88,60 D9.V8@88.5,60.5 ; 88,61 D9.V8@88.5,60.5 ; v5(88,72) D9.F8@88.5,72.5 v5(89,72) ; v5(88,72) D9.G8@88.5,71.5 v5(89,72) ; D9.V8@88.5,60.5 89,61 D9.V9@89.5,60.5 ; D9.V8@88.5,60.5 v5(89,60) ; v5(89,60) D9.W9@89.5,59.5 90,60 ; v5(89,60) D9.V9@89.5,60.5 ; v5(89,72) D9.G9@89.5,71.5 v5(90,72) ; v5(89,72) D9.F9@89.5,72.5 v5(90,72) ; D9.V9@89.5,60.5 90,61 ; D9.V9@89.5,60.5 90,60 ; 90,60 D9.W10@90.5,59.5 v5(91,60) ; 90,60 D9.V10@90.5,60.5 ; 90,61 D9.U10@90.5,61.5 91,61 ; 90,61 D9.V10@90.5,60.5 ; v5(90,72) D9.F10@90.5,72.5 v5(91,72) ; v5(90,72) D9.G10@90.5,71.5 v5(91,72) ; D9.V10@90.5,60.5 91,61 ; D9.V10@90.5,60.5 v5(91,60) ; v5(91,60) D9.W11@91.5,59.5 92,60 ; v5(91,60) D9.V11@91.5,60.5 ; 91,61 D9.U11@91.5,61.5 92,61 ; 91,61 D9.V11@91.5,60.5 ; v5(91,72) D9.G11@91.5,71.5 v5(92,72) ; v5(91,72) D9.F11@91.5,72.5 v5(92,72) ; D9.V11@91.5,60.5 92,61 ; D9.V11@91.5,60.5 92,60 ; 92,60 D9.W12@92.5,59.5 v5(93,60) ; 92,60 D9.V12@92.5,60.5 ; 92,61 D9.V12@92.5,60.5 ; v5(92,72) D9.F12@92.5,72.5 D9.F13@93.5,72.5 v5(94,72) ; v5(92,72) D9.G12@92.5,71.5 D9.G13@93.5,71.5 v5(94,72) ; D9.V12@92.5,60.5 v5(93,60) ; v5(93,60) D9.V13@93.5,60.5 94,60 ; v5(93,60) D9.W13@93.5,59.5 94,60 ; 94,60 D9.V14@94.5,60.5 95,60 ; 94,60 D9.W14@94.5,59.5 95,60 ; v5(94,72) D9.F14@94.5,72.5 v5(95,72) ; v5(94,72) D9.G14@94.5,71.5 v5(95,72) ; 95,60 D9.W15@95.5,59.5 v5(96,60) D9.V15@95.5,60.5 95,60 ; v5(95,72) D9.G15@95.5,71.5 v5(96,72) ; v5(95,72) D9.F15@95.5,72.5 v5(96,72) ; v5(96,72) D9.F16@96.5,72.5 v5(97,72) ; v5(96,72) D9.G16@96.5,71.5 v5(97,72) ; v5(97,60) D9.V17@97.5,60.5 98,60 ; v5(97,60) D9.V16@96.5,60.5 v5(96,60) D9.W16@96.5,59.5 v5(97,60) ; v5(97,72) D9.G17@97.5,71.5 v5(98,72) ; v5(97,72) D9.F17@97.5,72.5 v5(98,72) ; 98,60 D9.W18@98.5,59.5 99,60 ; 98,60 D9.V18@98.5,60.5 ; v5(98,72) D9.F18@98.5,72.5 v5(99,72) ; v5(98,72) D9.G18@98.5,71.5 ; D9.V18@98.5,60.5 v5(99,61) ; D9.V18@98.5,60.5 99,60 ; D9.G18@98.5,71.5 v5(99,71) ; D9.G18@98.5,71.5 v5(99,72) ; 99,60 D9.V19@99.5,60.5 v5(99,61) ; v5(99,63) D9.R18@98.5,63.5 v5(99,64) ; v5(99,63) D9.R19@99.5,63.5 v5(99,64) ; v5(99,64) D9.P19@99.5,64.5 v5(99,65) ; v5(99,64) D9.P18@98.5,64.5 v5(99,65) ; v5(99,65) D9.N18@98.5,65.5 v5(99,66) ; v5(99,65) D9.N19@99.5,65.5 v5(99,66) ; v5(99,66) D9.M19@99.5,66.5 v5(99,67) ; v5(99,66) D9.M18@98.5,66.5 v5(99,67) ; v5(99,67) D9.L18@98.5,67.5 v5(99,68) ; v5(99,67) D9.L19@99.5,67.5 v5(99,68) ; v5(99,68) D9.K19@99.5,68.5 v5(99,69) ; v5(99,68) D9.K18@98.5,68.5 v5(99,69) ; v5(99,69) D9.J18@98.5,69.5 98,70 D9.H18@98.5,70.5 v5(99,71) ; v5(99,71) D9.G19@99.5,71.5 v5(99,72)
  Solder Side w0.2: v3(301.8,43.3) R2.2@301.8,44.6 ; v3(303.1,43.3) R3.2@303.1,44.6 ; C42.1@305.9,43.4 C42.1@305.9,43.2 306.6,43.2 307.9,44.5 R41.2@307.9,45.7
  Solder Side w0.28: X8.114@72.81,96.865 72.81,98.79 ; X8.112@73.31,96.865 73.31,98.79 ; X8.110@73.81,96.865 73.81,98.69 ; X8.108@74.31,96.865 74.31,98.59 ; X8.106@74.81,96.865 74.81,98.79 ; 74.9,98.5 75.31,98.09 X8.104@75.31,97.9 ; X8.104@75.31,96.865 X8.104@75.31,97.9 ; X8.102@75.81,96.865 75.81,97.89 75.8,97.9 X8.104@75.31,97.9 ; v1@92.815,95 X8.54@92.815,96.865 ; 93.315,95 X8.52@93.315,96.865 ; v1@93.815,95 X8.50@93.815,96.865 ; 94.315,95 X8.48@94.315,96.865 ; v1@94.815,95 X8.46@94.815,96.865 ; 95.315,95 X8.44@95.315,96.865 ; v1@95.815,95 X8.42@95.815,96.865 ; v1@129.81,94.99 X3.114@129.81,96.865 129.81,98.59 ; X3.112@130.31,96.865 130.31,98.69 ; X3.110@130.81,96.865 130.81,98.59 ; X3.108@131.31,96.865 131.31,98.69 ; X3.106@131.81,96.865 131.81,98.69 ; X3.104@132.31,96.865 132.31,98.61 ; X3.102@132.81,96.865 132.81,98.49 ; v1@149.815,95.085 X3.54@149.815,96.865 ; 150.315,95.215 X3.52@150.315,96.865 ; v1@150.815,95.085 X3.50@150.815,96.865 ; 151.315,95.185 X3.48@151.315,96.865 ; v1@151.815,95.085 X3.46@151.815,96.865 ; 152.315,95.215 X3.44@152.315,96.865 ; v1@152.815,95.085 X3.42@152.815,96.865 ; X5.114@186.81,96.865 186.81,98.61 ; X5.112@187.31,96.865 187.31,98.71 ; X5.110@187.81,96.865 187.81,98.79 ; X5.108@188.31,96.865 188.31,98.79 ; X5.106@188.81,96.865 188.81,98.79 ; X5.104@189.31,96.865 189.31,98.79 ; X5.102@189.81,96.865 189.81,98.69 ; X5.54@206.815,96.865 206.815,98.615 ; X5.52@207.315,96.865 207.315,98.685 ; X5.50@207.815,96.865 207.815,98.715 ; X5.48@208.315,96.865 208.315,98.715 ; X5.46@208.815,96.865 208.815,98.715 ; X5.44@209.315,96.865 209.315,98.615 ; X5.42@209.815,96.865 209.815,98.485 ; X7.114@243.81,96.865 243.81,98.89 ; X7.112@244.31,96.865 244.31,98.71 ; X7.110@244.81,96.865 244.81,98.89 ; X7.108@245.31,96.865 245.31,98.89 ; X7.106@245.81,96.865 245.81,98.89 ; X7.104@246.31,96.865 246.31,98.79 ; X7.102@246.81,96.865 246.81,98.79 ; X7.54@263.815,96.865 263.815,98.615 ; X7.52@264.315,96.865 264.315,98.985 ; X7.50@264.815,96.865 264.815,98.815 ; X7.48@265.315,96.865 265.315,98.985 ; X7.46@265.815,96.865 265.815,98.915 ; X7.44@266.315,96.865 266.315,98.985 ; X7.42@266.815,96.865 266.815,99.185
  Solder Side w0.4: C101.1@86.2,60.8 87,60.8 C127.1@88,60.8 C142.1@89,60.8 ; v5(87,60) v5(87,61) ; v5(89,60) C142.1@89,60.8 ; v5(91,60) C128.1@91,60.8 ; v5(93,60) C107.1@93,60.8 ; v5(96,60) C106.1@96,60.8 ; v5(97,60) C130.1@97,60.8 ; C102.1@99.7,61.2 99.2,61.2 v5(99,61) 98.8,60.8 C130.1@97,60.8 ; C52.1@305.9,61 305.9,61.4 R37.1@307.5,63 R47.2@309.2,63 ; v5(87,64) 87,65 ; v5(87,64) C145.1@87.8,64 ; v5(87,64) v5(87,63) C109.1@87.8,63 C145.1@87.8,64 ; 87,65 v5(87,66) ; 87,65 C131.1@87.8,65 ; v5(87,66) C141.1@87.8,66 ; v5(87,66) v5(87,67) ; v5(87,67) C111.1@87.8,67 ; v5(87,67) v5(87,68) ; v5(87,68) C140.1@87.8,68 ; v5(87,68) v5(87,69) C133.1@87.8,69 C140.1@87.8,68 ; C145.1@87.8,64 C131.1@87.8,65 ; C131.1@87.8,65 C141.1@87.8,66 ; C141.1@87.8,66 C111.1@87.8,67 ; C111.1@87.8,67 C140.1@87.8,68 ; C137.1@88,71.2 v5(88,72) ; C137.1@88,71.2 87.8,71 v5(87,71) 86.4,71 C104.1@86.2,71.2 v5(87,72) v5(88,72) ; C137.1@88,71.2 C154.1@89,71.2 ; v5(88,72) v5(89,72) ; C142.1@89,60.8 C105.1@90,60.8 C128.1@91,60.8 ; C154.1@89,71.2 v5(89,72) ; C154.1@89,71.2 C115.1@90,71.2 ; v5(89,72) v5(90,72) ; C115.1@90,71.2 v5(90,72) ; C115.1@90,71.2 C136.1@91,71.2 ; v5(90,72) v5(91,72) ; C128.1@91,60.8 C144.1@92,60.8 C107.1@93,60.8 ; C136.1@91,71.2 v5(91,72) ; C136.1@91,71.2 C153.1@92,71.2 ; v5(91,72) v5(92,72) ; C153.1@92,71.2 v5(92,72) ; C153.1@92,71.2 C114.1@93,71.2 ; v5(92,72) 93,72 ; C107.1@93,60.8 C129.1@94,60.8 C152.1@95,60.8 C106.1@96,60.8 ; C114.1@93,71.2 93,72 ; C114.1@93,71.2 C138.1@94,71.2 ; 93,72 v5(94,72) ; C138.1@94,71.2 v5(94,72) ; C138.1@94,71.2 C151.1@95,71.2 ; v5(94,72) v5(95,72) ; C151.1@95,71.2 v5(95,72) ; C151.1@95,71.2 C113.1@96,71.2 ; v5(95,72) v5(96,72) ; C106.1@96,60.8 C130.1@97,60.8 ; C113.1@96,71.2 v5(96,72) ; C113.1@96,71.2 C135.1@97,71.2 ; v5(96,72) v5(97,72) ; C135.1@97,71.2 v5(97,72) ; C135.1@97,71.2 C150.1@98,71.2 ; v5(97,72) v5(98,72) ; C150.1@98,71.2 v5(98,72) ; C150.1@98,71.2 98.8,71.2 v5(99,71) 99.6,71 C103.1@99.8,71.2 v5(99,72) v5(98,72) ; C146.1@98.2,64 v5(99,64) ; C146.1@98.2,64 C132.1@98.2,65 ; C146.1@98.2,64 C110.1@98.2,63 v5(99,63) v5(99,64) ; C132.1@98.2,65 v5(99,65) v5(99,64) ; C132.1@98.2,65 C147.1@98.2,66 ; C147.1@98.2,66 v5(99,66) v5(99,67) ; C147.1@98.2,66 C112.1@98.2,67 ; C112.1@98.2,67 v5(99,67) ; C112.1@98.2,67 C148.1@98.2,68 ; C148.1@98.2,68 v5(99,68) ; C148.1@98.2,68 C134.1@98.2,69 v5(99,69) v5(99,68) ; v5(99,67) v5(99,68)
  Solder Side w0.8: C189.1@74.7,53.7 v1(74.7,55.2) v1(75.7,55.2) v1(76.7,55.2) 77.9,55.2 78.85,56.15 L2.1@78.85,56.9
  other v1: 75.8,46.2 76.8,46.2 77.8,46.2 78.8,46.2 75.8,47.2 76.8,47.2 77.8,47.2 78.8,47.2 75.9,61.7 77.1,61.7 75.9,62.8 77.1,62.8 129.9,94.9 130.9,94.9 131.9,94.9 132.9,94.9 138.3,94.9 139.3,94.9 140.3,94.9 141.3,94.9 150,94.9 151,94.9 152,94.9 153,94.9 158.1,94.9 159.1,94.9 160.1,94.9 161.1,94.9 92.8,95 93.8,95 94.8,95 95.8,95 101.4,95 102.4,95 103.4,95 104.4,95 246.5,101.8 247.5,101.8 248.5,101.8 250.4,101.8 251.4,101.8 269.3,101.8 270.3,101.8 271.3,101.8 272.3,101.8 273.3,101.8 71.3,101.9 72.3,101.9 73.3,101.9 74.3,101.9 79.6,101.9 80.6,101.9 81.6,101.9 82.6,101.9 83.6,101.9 189.5,102.1 190.6,102.1 191.7,102.1 192.8,102.1 193.9,102.1 211.1,102.1 212.1,102.1 213.1,102.1 214.1,102.1 215.1,102.1
  other v3: 300.5,40.7 301.8,40.7 303.1,40.7 304.4,40.7 300.5,42 301.8,42 303.1,42 304.4,42 300.5,43.3 304.4,43.3 300.5,58.5 301.8,58.5 303.1,58.5 304.4,58.5 300.5,59.8 301.8,59.8 303.1,59.8 304.4,59.8 300.5,61.1 301.8,61.1 303.1,61.1 304.4,61.1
